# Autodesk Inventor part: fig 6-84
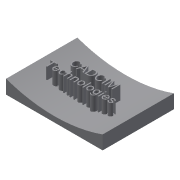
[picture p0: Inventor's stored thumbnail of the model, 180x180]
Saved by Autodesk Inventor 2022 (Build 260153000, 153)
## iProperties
Part Number: fig 6-84
Document SubType Name: Modeling
Created: 2002-12
Designer: deepak
Density: 1 g/cm^3
Material: Generic
Appearance: Default
Control State: 0
Master: False
Checked Out: False
Shininess: 64.0
Length Units: 11269
Angle Units: 11279
Time Units: 11290
Mass Units: 11283
Length Display Precision: 3
Angle Display Precision: 2
Compacted: True
Density: 0.0
Volumn: 0.0
Area: 0.0
PropertySet Name: Model Information
Author: deepak
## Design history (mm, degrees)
sketch "Sketch1"
  geometry: L1 (-39.922, 33.786)-(30.103, 33.786); L2 (30.103, 33.786)-(30.103, -17.894); L3 (30.103, -17.894)-(-39.922, -17.894); L4 (-39.922, -17.894)-(-39.922, 33.786)
  constraints: 8 end point, 2 parallel, 1 horizontal, 1 perpendicular
extrude "Extrusion1" new body sketch "Sketch1" distance "d0" = 10; taper "d1" = 0 deg
workplane "Work Plane1"
sketch "Sketch2"
  geometry: L1 (-37.656, 15.034)-(26.28, 15.034); L2 (26.28, 15.034)-(26.28, 10.168); L3 (26.28, 10.168)-(-37.656, 10.168); L4 (-37.656, 10.168)-(-37.656, 15.034)
  constraints: 2 other
sketch "Sketch3"
  geometry: L1 (70.026, 10)-(0, 10) reference; A1 r 105 centre (35.013, 108.99) between (0, 10) and (70.026, 10)
  constraints: 2 point on circle, 1 centre point
  dimensions: "d5" = 105 radius of A1
extrude "Extrusion2" cut sketch "Sketch3" extent not by distance; stored distance "d3" = 10; taper "d4" = 0 deg
emboss "Emboss4" sketch "Sketch2" dims "d14" = 1, "d15" = 0
body "Solid1"
other parameters: "d2" = 5
